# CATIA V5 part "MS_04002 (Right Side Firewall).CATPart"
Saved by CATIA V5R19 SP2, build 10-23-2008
Part number: MS_04002 (Right Side Firewall)
Publications: "Face", "Arête"
Bounding box of the stored display mesh (mm): x -1431.36 to 13.468, y -333.51 to -114.626, z -114 to 168
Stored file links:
  D:\EPSA\GIT\ELIZ-2022\01 - Maquette CATIA\MS_Miscellanous_Finish_Assembly\MS_A0400 (Firewall)\MS_04002 (Right Side Firewall).CATPart
  D:\EPSA\GIT\ELIZ-2022\01 - Maquette CATIA\MS_Miscellanous_Finish_Assembly\MS_A0400 (Firewall)\MS_A0400 (FireWall).CATProduct
  D:\EPSA\GIT\ELIZ-2022\01 - Maquette CATIA\FR_Frame_Body\FR_A0100 (frame)\Filaire.CATPart
  D:\EPSA\GIT\ELIZ-2022\01 - Maquette CATIA\MS_Miscellanous_Finish_Assembly\MS_A0400 (Firewall)\MS_04000 (test chape right side firewall).CATPart
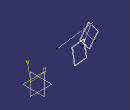
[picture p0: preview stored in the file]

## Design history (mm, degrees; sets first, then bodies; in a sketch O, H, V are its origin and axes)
Parameters
  `angle_pare-feu_lat` = 4.568 deg
SheetMetalParameters1: Thickness 1, BendRadius 1, KFactor 0.325257 {= log(min(100,max(20*SheetMetalParameters1.BendRadius,SheetMetalParameters1.Thickness)/SheetMetalParameters1.Thickness))/log(100)/2}, ReliefRadialLength 1, ReliefAxialLength 2, MinimumBendRadius 0
Set1
  DatumCurve1 to DatumCurve5: linked copy from another document
  Line1: linked copy from another document
Body1 (main body)
  Plane1: type 2Lines, Element1 DatumCurve1, Element2 DatumCurve2
  Plane2: type Offset, RefPlane Plane1, Offset 14
  Sketch1 on Plane2, origin (3.8523, -19.9899, -4.4703), H (-0.9819, -0.1892, 0), V (0.0406, -0.2106, 0.9767)
    line L1 (1416.0945, -106.0826) -> (1224.2187, 179.3837)
    line L2 (1086.9642, 122.5451) -> (1077.6265, -83.5435)
    line L3 (1224.2187, 179.3837) -> (1086.9642, 122.5451)
    line L4 (1077.6265, -83.5435) -> (1416.0945, -106.0826)
  Wall1: Thickness 1, Profile Sketch1
  d_NewWallOnEdge1: NewWallOnEdge_Edge edge [face of Wall1 | face of Wall1], NewWallOnEdge_Length 300, NewWallOnEdge_HeightLimitOffset 0, NewWallOnEdge_WidthOffset1 0, NewWallOnEdge_WidthOffset2 0, NewWallOnEdge_Angle 175.432 {= 180deg-`angle_pare-feu_lat`}, NewWallOnEdge_BendRadiusValue 1 {= SheetMetalParameters1.BendRadius}, NewWallOnEdge_BendTable SheetMetalParameters1, KFacteur 0.325257 {= log(min(100,max(20*d_NewWallOnEdge1.Radius,SheetMetalParameters1.Thickness)/SheetMetalParameters1.Thickness))/log(100)/2}
  Plane3: type Offset, RefPlane Plane1, Offset 15
  Sketch2 on face of d_NewWallOnEdge1, origin (12.4791, -106.4349, -18.0407), H (-0.9924, -0.1228, -0.001), V (0.0199, -0.1692, 0.9854)
    line L1 (1210.4094, 196.2058) -> (1400.425, 196.2058)
    line L2 (1400.425, 196.2058) -> (1217.6652, -113.4709)
    line L3 (1217.6652, -113.4709) -> (1219.7382, -116.8528)
    line L4 (1219.7382, -116.8528) -> (1657.2674, 142.855)
    line L5 (1657.2674, 142.855) -> (1503.3469, 393.9747)
    line L6 (1503.3469, 393.9747) -> (1212.7971, 221.5106)
    line L7 (1212.7971, 221.5106) -> (1210.4094, 196.2058)
    reference projected line E1 (1237.6901, -79.5398) -> (1392.5476, 182.858) from edge of DatumCurve3
    horizontal: L1 H
    parallelism: L5 L3, L6 L4
    coincidence: L2 E1
  Sketch3 on face of d_NewWallOnEdge1, origin (13.4676, -114.6262, -19.4493), H (-0.9932, -0.1167, 0), V (0.0194, -0.165, 0.9861)
    line L1 (1210.3812, 196.2225) -> (1400.3967, 196.2225)
    line L2 (1400.3967, 196.2225) -> (1217.4326, -113.3335)
    line L3 (1217.4326, -113.3335) -> (1219.5033, -116.7168)
    line L4 (1219.5033, -116.7168) -> (1657.2039, 142.7023)
    line L5 (1657.2039, 142.7023) -> (1503.4491, 393.9234)
    line L6 (1503.4491, 393.9234) -> (1212.7856, 221.6511)
    line L7 (1212.7856, 221.6511) -> (1210.3812, 196.2225)
    reference projected line E1 (1237.4798, -79.4157) -> (1392.5105, 182.8799) from edge of DatumCurve3
    horizontal: L1 H
    parallelism: L5 L3, L6 L4
    coincidence: L2 E1
  Pocket1: profile Sketch2, direction (0.1211, -0.9779, -0.1704), length 220
  Sketch4 on face of Wall1, origin (3.8523, -19.9899, -4.4703), H (0.9819, 0.1892, 0), V (0.0406, -0.2106, 0.9767)
    line L1 (-1327.8754, 43.683) -> (-1229.4854, -120.9456)
    line L2 (-1229.4854, -120.9456) -> (-1497.4945, -167.3352)
    line L3 (-1497.4945, -167.3352) -> (-1327.8754, 43.683)
    reference projected line E1 (-1248.0519, -89.8797) -> (-1401.3287, 166.5869) from edge of DatumCurve4
    coincidence: L1 E1
  Pocket2: profile Sketch4, direction (-0.1848, 0.9591, 0.2145), length 220
  Sketch5 on face of Wall1, origin (3.8523, -19.9899, -4.4703), H (0.9819, 0.1892, 0), V (0.0406, -0.2106, 0.9767)
    line L1 (-1324.6157, 41.7473) -> (-1231.5507, -106.027)
    line L2 (-1231.5507, -106.027) -> (-1272.9218, -119.4748)
    line L3 (-1272.9218, -119.4748) -> (-1377.1599, 24.0749)
    line L4 (-1377.1599, 24.0749) -> (-1324.6157, 41.7473)
  Pocket3: profile Sketch5, direction (-0.1848, 0.9591, 0.2145), length 220
  Sketch6 on face of d_NewWallOnEdge1, origin (12.5942, -107.4142, -18.2069), H (0.9924, 0.1228, 0.001), V (0.0199, -0.1692, 0.9854)
    line L1 (-1666.667, 178.3266) -> (-1746.5871, 74.912)
    line L2 (-1746.5871, 74.912) -> (-1399.619, -128.4113)
    line L3 (-1399.619, -128.4113) -> (-1322.4623, -28.5725)
    line L4 (-1322.4623, -28.5725) -> (-1666.667, 178.3266)
    parallelism: L3 L1
  Pocket4: profile Sketch6, direction (-0.1211, 0.9779, 0.1704), length 220
  Plane4: type 2Lines, Element1 DatumCurve5, Element2 Line1
  Plane5: type Offset, RefPlane Plane4, Offset 14, reversed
